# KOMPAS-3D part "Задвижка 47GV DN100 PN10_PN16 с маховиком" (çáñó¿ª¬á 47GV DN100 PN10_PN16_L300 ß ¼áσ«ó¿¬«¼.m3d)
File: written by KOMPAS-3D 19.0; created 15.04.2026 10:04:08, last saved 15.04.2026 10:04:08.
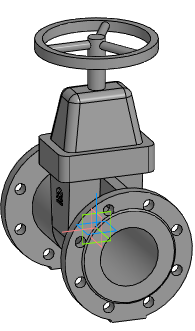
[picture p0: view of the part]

Document properties: Автор: Евгений; Полное имя файла: Z:\3.Личные\kachalov\3d для проектировщиков\2.1 Тип 47GV, 47GV.Z\Задвижка 47GV_DN40-DN600\stp_Задвижка 47GV\Задвижка 47GV DN100 PN10_PN16_L300 с маховиком.m3d

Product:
- Part/product: Задвижка 47GV DN100 PN10_PN16 с маховиком

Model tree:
1. Операция без истории:1  (labels: Задвижка 47GV DN100 PN10_PN16 с маховиком)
